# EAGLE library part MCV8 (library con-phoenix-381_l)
Mini-Combicon 3.81mm vertikal 8polig (ohne Gegenstecker)
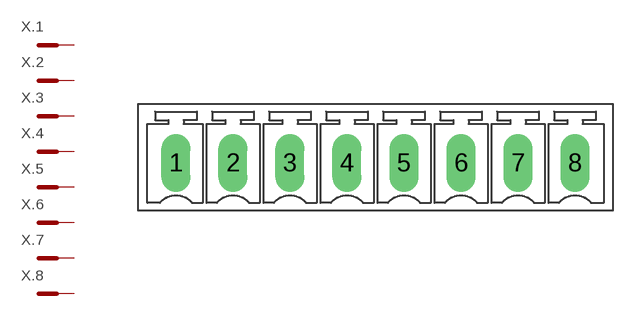
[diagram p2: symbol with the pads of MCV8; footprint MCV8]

Designator prefix X; gates .1=MCST .2=MCST .3=MCST .4=MCST .5=MCST .6=MCST .7=MCST .8=MCST

## MCV8  [MCV8]
1  .1:SK  pas
2  .2:SK  pas
3  .3:SK  pas
4  .4:SK  pas
5  .5:SK  pas
6  .6:SK  pas
7  .7:SK  pas
8  .8:SK  pas

## Footprint MCV8 (pad centres in mm)
Mini-Combicon 3.81mm vertikal 8-polig (ohne Gegenstecker)
drill 1.3 pad 1.905 long: 1 -13.335,0; 2 -9.525,0; 3 -5.715,0; 4 -1.905,0; 5 1.905,0; 6 5.715,0; 7 9.525,0; 8 13.335,0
